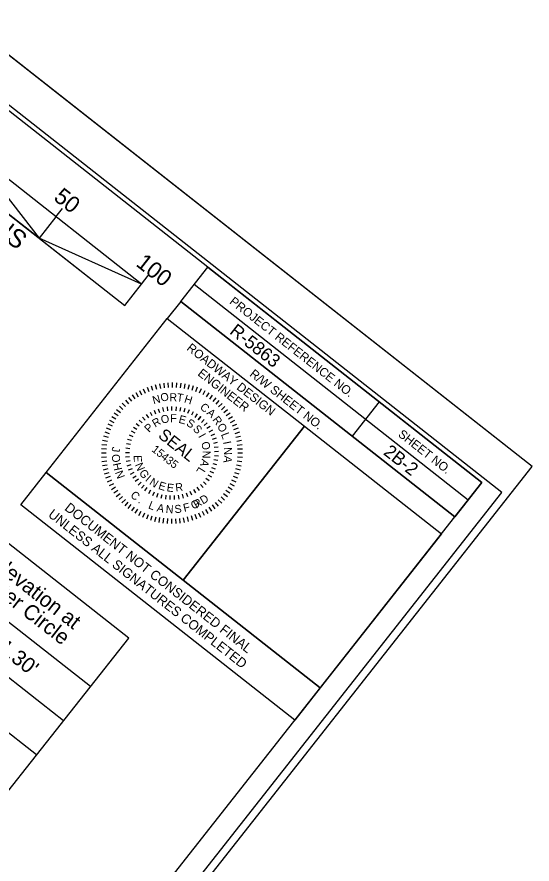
# Model space of a CAD drawing. Extents: x 556999 to 560450, y 504801 to 507732.
# Drawn here: x 558365.6 to 558602.1, y 506716.2 to 507105.3 of the extents above; entities that cross this region are included whole.
import ezdxf

# ---------------------------------------------------------------- set-up
doc = ezdxf.new("R2010")
doc.units = 0
for name, color, linetype in [('Old_Level_21', 7, 'Continuous'), ('Prop Horizontal Alignment Station Label', 7, 'Continuous'), ('Sheet Border Standard 30in CELL', 7, 'Continuous'), ('Sheet Cutting Line CELL', 7, 'Continuous'), ('Sheet Data Field CELL', 7, 'Continuous'), ('Sheet Plot Border Inside CELL', 7, 'Continuous'), ('Sheet Plot Border Outside CELL', 7, 'Continuous'), ('Sheet Sticker Exception Certification CELL', 7, 'Continuous'), ('Sheet Title CELL', 7, 'Continuous')]:
    doc.layers.add(name, color=color, linetype=linetype)

msp = doc.modelspace()

# ---------------------------------------------------------------- linework, layer by layer
at = {"layer": 'Old_Level_21'}
for p, q in [((558427.24, 506935.94), (558427.89, 506933.83)), ((558429.13, 506936.46), (558429.65, 506934.32)), ((558431.04, 506936.86), (558431.43, 506934.69)), ((558432.98, 506937.15), (558433.24, 506934.96)), ((558434.92, 506937.32), (558435.05, 506935.12)), ((558436.88, 506937.37), (558436.87, 506935.17)), ((558438.84, 506937.31), (558438.7, 506935.11)), ((558440.78, 506937.13), (558440.51, 506934.94)), ((558442.72, 506936.83), (558442.31, 506934.66)), ((558444.63, 506936.41), (558444.09, 506934.27)), ((558446.51, 506935.88), (558445.85, 506933.77)), ((558418.47, 506931.71), (558419.72, 506929.88)), ((558420.11, 506932.76), (558421.25, 506930.86)), ((558421.82, 506933.71), (558422.84, 506931.76)), ((558423.58, 506934.57), (558424.48, 506932.55)), ((558425.39, 506935.31), (558426.17, 506933.24)), ((558448.36, 506935.24), (558447.57, 506933.17)), ((558450.16, 506934.48), (558449.25, 506932.47)), ((558451.92, 506933.62), (558450.89, 506931.67)), ((558453.62, 506932.65), (558452.47, 506930.77)), ((558455.26, 506931.58), (558454, 506929.77)), ((558413.95, 506927.96), (558415.51, 506926.4)), ((558415.38, 506929.3), (558416.84, 506927.65)), ((558416.89, 506930.55), (558418.24, 506928.81)), ((558456.83, 506930.42), (558455.46, 506928.69)), ((558458.33, 506929.16), (558456.86, 506927.51)), ((558459.75, 506927.82), (558458.19, 506926.26)), ((558411.35, 506925.05), (558413.08, 506923.68)), ((558412.61, 506926.54), (558414.26, 506925.08)), ((558426.69, 506923.8), (558427.56, 506922.18)), ((558428.56, 506924.69), (558429.26, 506922.99)), ((558430.49, 506925.39), (558431.03, 506923.63)), ((558432.49, 506925.9), (558432.86, 506924.1)), ((558434.53, 506926.22), (558434.72, 506924.38)), ((558436.59, 506926.34), (558436.6, 506924.49)), ((558438.65, 506926.25), (558438.48, 506924.42)), ((558440.69, 506925.97), (558440.35, 506924.17)), ((558442.7, 506925.5), (558442.19, 506923.73)), ((558444.65, 506924.83), (558443.97, 506923.12)), ((558446.53, 506923.98), (558445.69, 506922.34)), ((558461.09, 506926.39), (558459.43, 506924.93)), ((558462.33, 506924.88), (558460.59, 506923.53)), ((558408.15, 506920.13), (558410.1, 506919.1)), ((558409.12, 506921.83), (558411, 506920.69)), ((558410.19, 506923.47), (558412, 506922.21)), ((558421.73, 506920.13), (558423.03, 506918.83)), ((558423.27, 506921.51), (558424.43, 506920.09)), ((558424.92, 506922.74), (558425.95, 506921.21)), ((558448.31, 506922.95), (558447.32, 506921.4)), ((558449.99, 506921.75), (558448.86, 506920.31)), ((558448.86, 506920.31), (558449.99, 506921.75)), ((558451.55, 506920.39), (558450.28, 506919.07)), ((558463.49, 506923.3), (558461.67, 506922.05)), ((558464.54, 506921.66), (558462.65, 506920.52)), ((558465.5, 506919.95), (558463.54, 506918.93)), ((558406.53, 506916.57), (558408.6, 506915.78)), ((558407.29, 506918.38), (558409.3, 506917.46)), ((558419.1, 506916.96), (558420.63, 506915.93)), ((558420.34, 506918.61), (558421.76, 506917.44)), ((558452.97, 506918.9), (558451.57, 506917.7)), ((558454.23, 506917.27), (558452.73, 506916.21)), ((558466.35, 506918.19), (558464.33, 506917.29)), ((558467.09, 506916.38), (558465.03, 506915.6)), ((558405.36, 506912.84), (558407.5, 506912.31)), ((558405.89, 506914.73), (558408, 506914.06)), ((558417.13, 506913.34), (558418.82, 506912.62)), ((558418.03, 506915.2), (558419.65, 506914.32)), ((558455.34, 506915.53), (558453.74, 506914.62)), ((558456.27, 506913.69), (558454.59, 506912.94)), ((558467.73, 506914.53), (558465.62, 506913.88)), ((558468.24, 506912.64), (558466.1, 506912.12)), ((558404.64, 506909), (558406.83, 506908.73)), ((558404.94, 506910.93), (558407.11, 506910.53)), ((558415.9, 506909.41), (558417.7, 506909.03)), ((558416.42, 506911.41), (558418.17, 506910.85)), ((558457.02, 506911.77), (558455.27, 506911.18)), ((558457.58, 506909.78), (558455.78, 506909.37)), ((558468.65, 506910.73), (558466.48, 506910.34)), ((558468.94, 506908.79), (558466.74, 506908.53)), ((558404.39, 506905.1), (558406.6, 506905.09)), ((558404.46, 506907.05), (558406.66, 506906.91)), ((558415.43, 506905.32), (558417.28, 506905.29)), ((558415.57, 506907.38), (558417.39, 506907.17)), ((558457.94, 506907.75), (558456.11, 506907.51)), ((558458.11, 506905.7), (558456.27, 506905.64)), ((558469.11, 506906.84), (558466.9, 506906.72)), ((558469.16, 506904.89), (558466.95, 506904.89)), ((558404.45, 506903.14), (558406.65, 506903.27)), ((558404.62, 506901.19), (558406.81, 506901.45)), ((558415.51, 506903.26), (558417.34, 506903.41)), ((558415.77, 506901.21), (558417.58, 506901.54)), ((558457.85, 506901.59), (558456.03, 506901.88)), ((558458.08, 506903.64), (558456.24, 506903.75)), ((558468.91, 506900.99), (558466.72, 506901.26)), ((558469.09, 506902.93), (558466.89, 506903.07)), ((558404.91, 506899.26), (558407.08, 506899.65)), ((558405.31, 506897.34), (558407.45, 506897.86)), ((558416.23, 506899.2), (558418, 506899.7)), ((558416.89, 506897.25), (558418.6, 506897.92)), ((558456.8, 506897.6), (558455.07, 506898.24)), ((558457.42, 506899.57), (558455.64, 506900.03)), ((558468.19, 506897.14), (558466.05, 506897.68)), ((558468.61, 506899.05), (558466.44, 506899.46)), ((558405.83, 506895.46), (558407.94, 506896.11)), ((558406.46, 506893.61), (558408.53, 506894.38)), ((558407.2, 506891.8), (558409.22, 506892.7)), ((558417.73, 506895.36), (558419.37, 506896.19)), ((558418.75, 506893.57), (558420.3, 506894.55)), ((558421.38, 506893.02), (558419.92, 506891.89)), ((558453.85, 506892.18), (558452.38, 506893.29)), ((558455.01, 506893.89), (558453.44, 506894.85)), ((558455.99, 506895.7), (558454.34, 506896.5)), ((558467.02, 506893.41), (558464.96, 506894.2)), ((558467.66, 506895.26), (558465.56, 506895.92)), ((558408.06, 506890.04), (558410.01, 506891.06)), ((558409.01, 506888.33), (558410.9, 506889.46)), ((558421.28, 506890.32), (558422.61, 506891.58)), ((558422.77, 506888.89), (558423.97, 506890.28)), ((558424.38, 506887.61), (558425.45, 506889.11)), ((558449.47, 506887.83), (558448.38, 506889.31)), ((558449.89, 506890.55), (558451.12, 506889.19)), ((558452.53, 506890.6), (558451.18, 506891.83)), ((558464.43, 506888.15), (558462.55, 506889.3)), ((558465.4, 506889.85), (558463.45, 506890.88)), ((558466.26, 506891.6), (558464.26, 506892.52)), ((558410.06, 506886.68), (558411.89, 506887.93)), ((558411.22, 506885.1), (558412.96, 506886.46)), ((558412.47, 506883.6), (558414.12, 506885.05)), ((558426.12, 506886.5), (558427.04, 506888.09)), ((558427.95, 506885.56), (558428.71, 506887.24)), ((558429.87, 506884.8), (558430.47, 506886.54)), ((558431.85, 506884.23), (558432.28, 506886.02)), ((558433.88, 506883.85), (558434.13, 506885.67)), ((558435.94, 506883.67), (558436.01, 506885.5)), ((558438, 506883.68), (558437.89, 506885.52)), ((558440.05, 506883.9), (558439.77, 506885.72)), ((558442.07, 506884.31), (558441.61, 506886.1)), ((558444.04, 506884.92), (558443.41, 506886.65)), ((558445.94, 506885.72), (558445.15, 506887.38)), ((558447.76, 506886.69), (558446.81, 506888.27)), ((558460.95, 506883.44), (558459.3, 506884.91)), ((558462.2, 506884.94), (558460.47, 506886.31)), ((558463.37, 506886.51), (558461.56, 506887.77)), ((558413.81, 506882.17), (558415.37, 506883.72)), ((558415.22, 506880.82), (558416.69, 506882.47)), ((558416.72, 506879.57), (558418.09, 506881.3)), ((558456.67, 506879.44), (558455.31, 506881.18)), ((558458.17, 506880.68), (558456.72, 506882.34)), ((558459.6, 506882.02), (558458.05, 506883.58)), ((558418.3, 506878.4), (558419.56, 506880.21)), ((558419.94, 506877.33), (558421.08, 506879.22)), ((558421.63, 506876.37), (558422.67, 506878.32)), ((558423.39, 506875.5), (558424.3, 506877.51)), ((558449.97, 506875.42), (558449.07, 506877.44)), ((558451.73, 506876.27), (558450.71, 506878.23)), ((558453.44, 506877.22), (558452.31, 506879.12)), ((558455.09, 506878.28), (558453.84, 506880.1)), ((558425.2, 506874.75), (558425.99, 506876.81)), ((558427.04, 506874.11), (558427.71, 506876.21)), ((558428.93, 506873.58), (558429.46, 506875.72)), ((558430.84, 506873.16), (558431.24, 506875.33)), ((558432.77, 506872.86), (558433.04, 506875.05)), ((558434.72, 506872.67), (558434.86, 506874.88)), ((558436.67, 506872.61), (558436.68, 506874.82)), ((558438.63, 506872.66), (558438.5, 506874.86)), ((558440.58, 506872.83), (558440.32, 506875.02)), ((558442.51, 506873.12), (558442.12, 506875.29)), ((558444.43, 506873.53), (558443.9, 506875.67)), ((558446.31, 506874.04), (558445.66, 506876.15)), ((558448.16, 506874.67), (558447.39, 506876.74))]:
    msp.add_line(p, q, dxfattribs=at)
at = {"layer": 'Prop Horizontal Alignment Station Label'}
for p, q in [((558142.86, 507035.66), (558416.94, 506820.13)), ((558125.3, 507013.43), (558399.37, 506797.89)), ((558112.9, 506997.73), (558386.98, 506782.2)), ((558100.51, 506982.04), (558374.58, 506766.5)), ((558416.82, 506819.98), (558027.36, 506326.9))]:
    msp.add_line(p, q, dxfattribs=at)
at = {"layer": 'Sheet Border Standard 30in CELL'}
for p, q in [((558447, 506982.52), (558572.8, 506883.59)), ((558440.81, 506974.66), (558434.63, 506966.8)), ((558440.81, 506974.66), (558566.61, 506875.73)), ((558440.81, 506974.66), (558566.61, 506875.73)), ((558531.81, 506928.54), (558519.45, 506912.82)), ((558497.55, 506917.32), (558441.94, 506846.61))]:
    msp.add_line(p, q, dxfattribs=at)
for points in [[(558579, 506891.48), (557635.74, 507633.27), (557116.49, 506972.99), (558059.75, 506231.2)], [(558453.2, 506990.41), (558579, 506891.48), (558566.61, 506875.73), (558440.81, 506974.66)], [(558434.63, 506966.8), (558497.55, 506917.32), (558441.91, 506846.58), (558379, 506896.06)], [(558497.55, 506917.32), (558560.43, 506867.87), (558504.8, 506797.12), (558441.91, 506846.58)]]:
    msp.add_lwpolyline(points, close=True, dxfattribs=at)
at = {"layer": 'Sheet Cutting Line CELL'}
msp.add_line((558602.06, 506898.8), (557543.09, 507731.58), dxfattribs=at)
at = {"layer": 'Sheet Data Field CELL'}
for p, q in [((558383.51, 507013.48), (558386.59, 507017.4)), ((558422.8, 506982.56), (558425.9, 506986.5))]:
    msp.add_line(p, q, dxfattribs=at)
at = {"layer": 'Sheet Plot Border Inside CELL'}
msp.add_lwpolyline([(558588.12, 506886.9), (557540.16, 507711.03), (557018.38, 507047.54), (558066.35, 506223.41)], close=True, dxfattribs=at)
at = {"layer": 'Sheet Plot Border Outside CELL'}
msp.add_lwpolyline([(558602.06, 506898.8), (557543.09, 507731.58), (556999.11, 507039.85), (558058.08, 506207.07)], close=True, dxfattribs=at)
at = {"layer": 'Sheet Sticker Exception Certification CELL'}
for p, q in [((558367.38, 506881.28), (558379, 506896.06)), ((558379, 506896.06), (558504.79, 506797.13)), ((558493.17, 506782.35), (558367.38, 506881.28)), ((558504.78, 506797.12), (558493.16, 506782.35))]:
    msp.add_line(p, q, dxfattribs=at)
at = {"layer": 'Sheet Title CELL'}
for p, q in [((558422.79, 506982.57), (558304.88, 507075.29)), ((558297.16, 507065.47), (558415.06, 506972.73)), ((558383.49, 507013.48), (558386.57, 507017.4)), ((558383.49, 507013.48), (558375.76, 507003.65)), ((558422.79, 506982.57), (558425.88, 506986.5)), ((558415.06, 506972.73), (558422.79, 506982.57))]:
    msp.add_line(p, q, dxfattribs=at)
for points in [[(558344.18, 507044.38), (558375.76, 507003.65), (558336.45, 507034.55)], [(558422.79, 506982.57), (558375.76, 507003.65), (558415.06, 506972.73)]]:
    msp.add_lwpolyline(points, close=True, dxfattribs=at)

# ---------------------------------------------------------------- texts
at = {"layer": 'Old_Level_21'}
for s, height, rotation, p in [('N', 3.68, 15.415, (558428.36, 506927.36)), ('O', 3.68, 13.4556, (558431.94, 506928.49)), ('R', 3.68, 0.3989, (558435.57, 506928.79)), ('T', 3.68, 352.2379, (558438.78, 506928.87)), ('H', 3.68, 342.806, (558442.1, 506928.3)), ('C', 3.68, 319.0953, (558449.3, 506925.62)), ('A', 3.68, 319.0953, (558452.41, 506923.08)), ('R', 3.68, 30.5714, (558429.02, 506916.67)), ('O', 3.68, 15.2752, (558432.21, 506918.37)), ('F', 3.68, 359.9789, (558435.96, 506919.18)), ('E', 3.68, 344.6827, (558439.56, 506918.99)), ('S', 3.68, 329.3864, (558443.05, 506917.85)), ('R', 3.68, 307.086, (558455.13, 506920.24)), ('P', 3.68, 45.8677, (558426.33, 506914.16)), ('S', 3.68, 314.0902, (558446.12, 506915.81)), ('O', 3.68, 304.0292, (558457.27, 506917.2)), ('SEAL', 5.518, 321.7383, (558430.04, 506912.41)), ('I', 3.68, 298.7939, (558448.7, 506912.77)), ('L', 3.68, 290.8929, (558459.2, 506913.6)), ('O', 3.68, 283.4977, (558450.14, 506909.81)), ('I', 3.68, 281.3174, (558460.2, 506910.09)), ('J', 3.68, 265.6733, (558409.29, 506907.98)), ('O', 3.68, 273.7451, (558409.13, 506904.38)), ('15435', 3.676, 321.7383, (558427.15, 506906.08)), ('N', 3.68, 268.2014, (558450.84, 506906.12)), ('N', 3.68, 272.0229, (558460.58, 506907.59)), ('H', 3.68, 282.3879, (558409.56, 506900.09)), ('E', 3.68, 271.8084, (558419.2, 506903.98)), ('N', 3.68, 292.6635, (558419.73, 506899.67)), ('A', 3.68, 252.9052, (558450.56, 506902.51)), ('A', 3.68, 262.2554, (558460.8, 506903.96)), ('N', 3.68, 291.0605, (558410.58, 506896.12)), ('G', 3.68, 301.4297, (558421.49, 506896.08)), ('L', 3.68, 237.609, (558449.24, 506898.92)), ('I', 3.68, 319.5245, (558424.2, 506892.45)), ('N', 3.68, 327.1542, (558426.08, 506890.81)), ('E', 3.68, 342.5462, (558430.24, 506888.57)), ('E', 3.68, 352.5321, (558434.18, 506887.47)), ('R', 3.68, 6.3032, (558438.51, 506887.31)), ('C', 3.68, 317.8283, (558417.39, 506885.27)), (' RD', 3.676, 31.4107, (558446.79, 506878.74)), ('.', 3.68, 325.5706, (558420.92, 506882.37)), ('L', 3.68, 338.3549, (558425.62, 506879.7)), ('A', 3.68, 347.3575, (558429.57, 506878.29)), ('N', 3.68, 356.1801, (558433.81, 506877.5)), ('S', 3.68, 5.0627, (558438.09, 506877.37)), ('F', 3.68, 13.9454, (558442.42, 506877.93)), ('O ', 3.676, 22.738, (558446.36, 506879.05))]:
    msp.add_text(s, height=height, rotation=rotation, dxfattribs=at).set_placement(p)
at = {"layer": 'Prop Horizontal Alignment Station Label'}
for s, rotation, p in [('Elevation at', 322.1027, (558352.89, 506853.77)), ('Outer Circle', 322.1027, (558347, 506847.11)), ("1881.30'", 321.7725, (558344.05, 506824.26))]:
    msp.add_text(s, height=7, rotation=rotation, dxfattribs=at).set_placement(p)
at = {"layer": 'Sheet Border Standard 30in CELL'}
for s, height, p in [('PROJECT REFERENCE NO.', 4.0001, (558462.86, 506973.96)), ('ROADWAY DESIGN', 4.0001, (558443.22, 506952.62)), ('ENGINEER', 4, (558448.26, 506940.97)), ('R/W SHEET NO.', 4.0001, (558472.11, 506940.69)), ('SHEET NO.', 4, (558540.25, 506913))]:
    msp.add_text(s, height=height, rotation=321.8181, dxfattribs=at).set_placement(p)
at = {"layer": 'Sheet Data Field CELL'}
for s, p in [('R-5863   ', (558462.81, 506960.16)), ('2B-2 ', (558533.46, 506904.65))]:
    msp.add_text(s, height=6, rotation=321.8181, dxfattribs=at).set_placement(p)
at = {"layer": 'Sheet Sticker Exception Certification CELL'}
for s, p in [('DOCUMENT NOT CONSIDERED FINAL', (558387.13, 506879.13)), ('UNLESS ALL SIGNATURES COMPLETED', (558379.59, 506876.1))]:
    msp.add_text(s, height=4.4, rotation=321.8181, dxfattribs=at).set_placement(p)
at = {"layer": 'Sheet Title CELL'}
for s, height, p in [('PLANS', 8.5, (558336.64, 507021.04)), ('50', 7.5, (558382.04, 507021.53)), ('100', 7.5, (558419.8, 506991.3))]:
    msp.add_text(s, height=height, rotation=321.8181, dxfattribs=at).set_placement(p)

doc.saveas('drawing.dxf')
